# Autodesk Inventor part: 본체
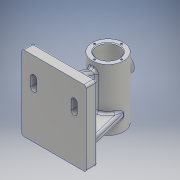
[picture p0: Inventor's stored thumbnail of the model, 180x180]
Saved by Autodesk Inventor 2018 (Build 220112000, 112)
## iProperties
Created: 2022-06
Part Number: 본체
Material: 알루미늄 6061
Document SubType Name: Modeling
Designer: home
Density: 2.7 g/cm^3
Appearance: 알루미늄 - 평지
Mass: 632.892 g
Surface Area: 512.994 cm^2
Volume: 234.404 cm^3
Author: home
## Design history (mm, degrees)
sketch "스케치1"
  geometry: L1 (-43, 50)-(43, 50); L2 (43, 50)-(43, -50); L3 (43, -50)-(-43, -50); L4 (-43, -50)-(-43, 50); L5 (-43, 50)-(43, -50); L6 (43, 50)-(-43, -50); 1 further point
  constraints: 12 end point, 2 midpoint, 2 parallel, 1 horizontal, 1 perpendicular
  dimensions: "d0" = 86 distance of L2.end L3.end; "d1" = 100 distance of L1.end L2.end
extrude "돌출1" new body sketch "스케치1" distance "d2" = 15; taper "d3" = 0 deg
sketch "스케치2"
  geometry: L1 (72, 71.237)-(72, -101.318); L2 (83.5, -50)-(93, -50); L3 (0, -50)-(15, -50) reference; L4 (83.5, -50)-(83.5, -30); L5 (93, -50)-(93, -20.658); L6 (93, -20.658)-(93, 32); L7 (93, 32)-(86.5, 32); L8 (86.5, 32)-(86.5, -30); L9 (86.5, -30)-(83.5, -30); 1 further point
  constraints: 16 end point, 3 perpendicular, 3 vertical, 2 horizontal
  dimensions: "d4" = 144 diameter of point (0, 0) L1; "d5" = 0 distance between parallel lines of L2 L3; "d6" = 23 diameter of L4 L1; "d7" = 42 diameter of L5 L1; "d8" = 82 distance of L2.end L6.end; "d9" = 29 diameter of L8 L1; "d10" = 62 vertical distance of L7.end L4.end
revolve "회전1" sketch "스케치2" stored, may be unused: angle "d11" = 90 deg
node "작업 평면1"
sketch "스케치5"
  geometry: L1 (0, 0)-(0, 15) reference; L2 (86, 15)-(0, 15) reference; L3 (8, 15)-(22, 72); L4 (43, 72)-(0, 72); L5 (43, 0)-(43, 72); L6 (0, 0)-(86, 0) reference; L7 (78, 15)-(64, 72); L8 (8, 15)-(78, 15); L9 (8, 15)-(78, 15); A1 r 21 centre (43, 72) between (22, 72) and (64, 72); A2 r 21 centre (43, 72) between (22, 72) and (64, 72)
  constraints: 12 end point, 4 point on circle, 2 centre point, 2 horizontal, 2 symmetric about line, 1 collinear, 1 concentric, 1 horizontal alignment, 1 perpendicular, 1 other
  dimensions: "d13" = 8 distance from line of L1 L3.start; "d14" = 0 distance from line of L2 L3.start; "d15" = 103.799 deg angle of L2 L3
extrude "돌출2" join sketch "스케치5" distance "d16" = 10; taper "d17" = 0 deg
node "작업 평면2"
sketch "스케치6"
  geometry: L1 (0, 0)-(0, 15) reference; L2 (100, 15)-(0, 15) reference; L3 (15, 15)-(28.823, 52.978); L4 (75, 72)-(75, 15) reference; L5 (15, 15)-(75, 15); L6 (75, 52.978)-(28.823, 52.978); L7 (18, 51)-(100, 51) reference; L8 (75, 52.978)-(75, 15); 2 further points
  constraints: 8 end point, 1 collinear, 1 parallel, 1 point on line
  dimensions: "d18" = 15 distance from line of L1 L3.start; "d19" = 0 distance from line of L2 L3.start; "d20" = 70 deg angle of L2 L3; "d21" = 0 distance from line of L4 point (75, 15); "d22" = 0 distance of L4.end point (75, 15); "d23" = 46.17723 distance of L6.start L3.end
extrude "돌출3" join sketch "스케치6" stored distance "d24" = 10; taper "d25" = 0 deg
node "작업 평면3"
sketch "스케치7"
  geometry: L1 (-21, 32)-(21, 32) reference; C1 r 11 at (0, 7); 2 further points
  constraints: 1 centre point, 1 coincident
  dimensions: "d27" = 25 distance from line of L1 point (0, 7); "d28" = 0 horizontal distance of point (0, 0) point (0, 7); "d29" = 22 diameter of C1
extrude "돌출4" join sketch "스케치7" stored distance "d30" = 10; taper "d31" = 0 deg
sketch "스케치8"
  geometry: C1 r 11 at (0, 0) reference; C2 r 7 at (0, 0); 1 further point
  constraints: 1 centre point, 1 coincident
  dimensions: "d32" = 14 diameter of C2
extrude "돌출5" cut sketch "스케치8" distance "d33" = 4; taper "d34" = 0 deg
sketch "스케치9"
  geometry: C1 r 7 at (0, 0) reference; 1 further point
hole "구멍1" sketch "스케치9" at (0, 0) diameter "d35" = 4.917; stored, may be unused: countersink angle "d39" = 90 deg, drill point angle "d41" = 0 deg; dims "d36" = 15, "d37" = 4, "d38" = 2, "d40" = 15
fillet "모깎기1" dims "d42" = 1
sketch "스케치10"
  geometry: C1 r 14.5 at (0, 0) reference; C2 r 21 at (0, 0) reference; 2 further points
  dimensions: "d43" = 0 horizontal distance of C1.centre point (0, 18); "d44" = 18 distance of C1.centre point (0, 18)
hole "구멍2" sketch "스케치10" at (0, 18) diameter "d45" = 2.459; stored, may be unused: countersink angle "d49" = 90 deg, drill point angle "d51" = 118 deg; dims "d46" = 8, "d47" = 4, "d48" = 2, "d50" = 10
sketch "스케치11"
  geometry: C1 r 21 at (0, 0) reference; C2 r 11.5 at (0, 0) reference; 2 further points
  dimensions: "d55" = 0 horizontal distance of C1.centre point (0, 18); "d56" = 18 distance of C1.centre point (0, 18)
hole "구멍3" sketch "스케치11" at (0, 18) diameter "d57" = 2.459; stored, may be unused: countersink angle "d61" = 90 deg, drill point angle "d63" = 118 deg; dims "d58" = 8, "d59" = 4, "d60" = 2, "d62" = 10
node "작업 평면4"
sketch "스케치12"
  geometry: L1 (-43, -50)-(43, -50) reference; L2 (27, -24)-(27, -12); L3 (34, -24)-(34, -12); L4 (20, -12)-(20, -24); L5 (27, -24)-(27, -12); L6 (31, -24)-(31, -12); L7 (23, -12)-(23, -24); L8 (0, -57.693)-(0, 78.656); L9 (-20, -12)-(-20, -24); L10 (-23, -12)-(-23, -24); L11 (-31, -24)-(-31, -12); L12 (-34, -24)-(-34, -12); A1 r 7 centre (27, -24) between (20, -24) and (34, -24); A2 r 7 centre (27, -12) between (34, -12) and (20, -12); A3 r 4 centre (27, -24) between (23, -24) and (31, -24); A4 r 4 centre (27, -12) between (31, -12) and (23, -12); A5 r 7 centre (-27, -24) between (-34, -24) and (-20, -24); A6 r 7 centre (-27, -12) between (-20, -12) and (-34, -12); A7 r 4 centre (-27, -24) between (-31, -24) and (-23, -24); A8 r 4 centre (-27, -12) between (-23, -12) and (-31, -12); 3 further points
  constraints: 26 end point, 16 point on circle, 10 symmetric about line, 8 centre point, 8 tangent, 3 equal length, 2 midpoint, 2 vertical, 4 other
  dimensions: "d68" = 27 horizontal distance of L2.start point (0, 0); "d69" = 26 distance from line of L1 L2.start; "d70" = 12 distance of L2.start L2.end; "d71" = 14 diameter of A2; "d72" = 8 diameter of A4; "d73" = 0 distance from line of L8 point (0, 0)
extrude "돌출6" join sketch "스케치12" stored distance "d74" = 4; taper "d75" = 0 deg
sketch "스케치13"
  geometry: L1 (23, -12)-(23, -24) reference; L2 (31, -24)-(31, -12) reference; L3 (-23, -24)-(-23, -12) reference; L4 (-31, -12)-(-31, -24) reference; A1 r 4 centre (27, -24) between (23, -24) and (31, -24) reference; A2 r 4 centre (27, -12) between (31, -12) and (23, -12) reference; A3 r 4 centre (-27, -12) between (-23, -12) and (-31, -12) reference; A4 r 4 centre (-27, -24) between (-31, -24) and (-23, -24) reference; 1 further point
extrude "돌출7" cut sketch "스케치13" distance "d76" = 18; taper "d77" = 0 deg
fillet "모깎기2" dims "d78" = 3
fillet "모깎기3" dims "d79" = 3
fillet "모깎기4" dims "d80" = 3
fillet "모깎기5" dims "d81" = 3
fillet "모깎기6" dims "d82" = 3
chamfer "모따기1" distance "d83" = 1; stored, may be unused: second distance "d84" = 2, angle "d85" = 45 deg
node "작업 평면5"
sketch "스케치14"
  geometry: L1 (80, 0)-(0, 0) reference; 2 further points
  constraints: 1 other
  dimensions: "d87" = 6 distance from line of L1 point (40, 6); "d88" = 0 horizontal distance of point (40, 6) point (40, 0)
feature "엠보싱1" sketch "스케치14" dims "d0" = 86, "d1" = 100, "d89" = 0.5, "d90" = 0
node "솔리드1"
pattern_circular "원형 패턴1" dims angle "d53" = 360 deg
pattern_circular "원형 패턴2" dims angle "d65" = 360 deg
node "투영된 루프1"
node "투영된 루프2"
node "투영된 루프3"
node "투영된 루프4"
node "투영된 루프5"
node "투영된 루프6"
other parameters: "d12" = -15, "d26" = -96, "d67" = 3, "d86" = 1
